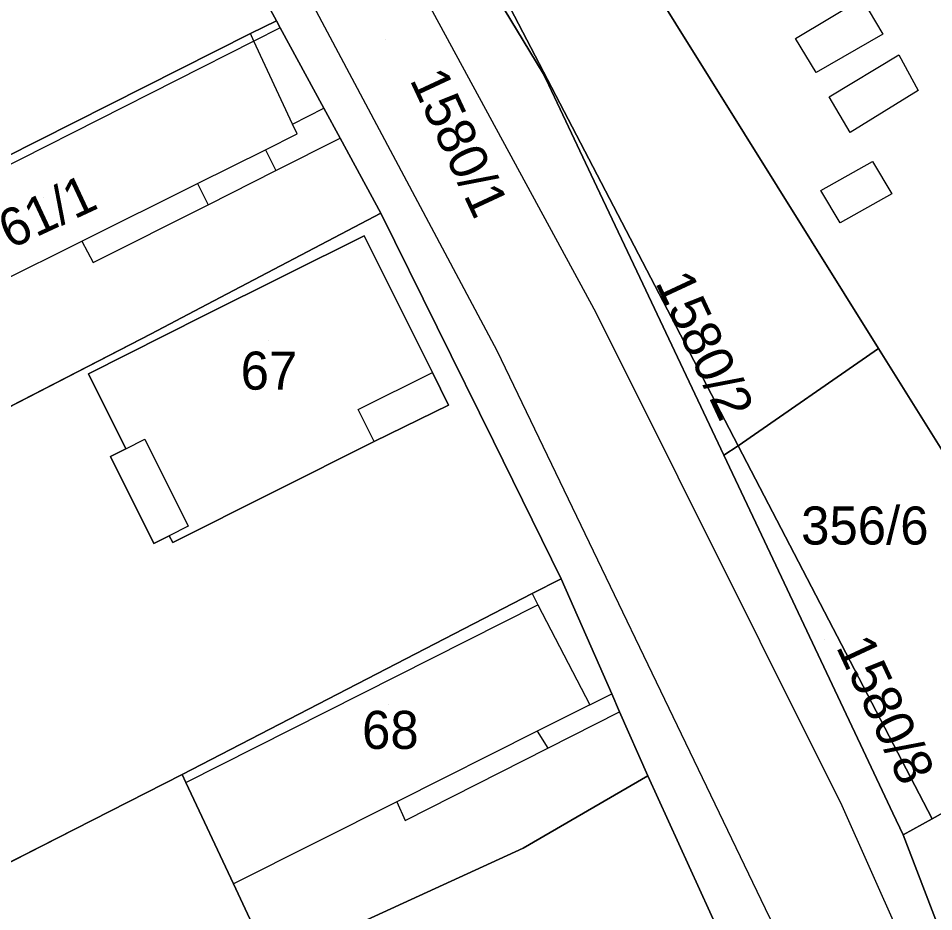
# Model space of a CAD drawing. Extents: x -263943 to -261149, y -1236934 to -1230686.
# Drawn here: x -262794.63 to -262746.54, y -1235729.03 to -1235682.08 of the extents above; entities that cross this region are included whole.
import ezdxf

# ---------------------------------------------------------------- set-up
doc = ezdxf.new("R2010")
doc.units = 0
for name, color, linetype in [('body_kn', 7, 'Continuous'), ('kladpar_druhypozemkov', 7, 'Continuous'), ('kladpar_hranice', 7, 'Continuous'), ('kladpar_parcelnecisla', 7, 'Continuous'), ('kladpar_plochy', 7, 'Continuous'), ('zappar_hrandruhpozemk', 7, 'Continuous')]:
    doc.layers.add(name, color=color, linetype=linetype)

msp = doc.modelspace()

# ---------------------------------------------------------------- linework, layer by layer
at = {"layer": 'body_kn'}
for p, q in [((-262781.07, -1235682.21), (-262781.07, -1235682.21)), ((-262782.43, -1235682.89), (-262782.43, -1235682.89)), ((-262780.87, -1235682.58), (-262780.87, -1235682.58)), ((-262780.87, -1235682.58), (-262780.87, -1235682.58)), ((-262749.22, -1235682.91), (-262749.22, -1235682.91)), ((-262782.25, -1235683.28), (-262782.25, -1235683.28)), ((-262782.25, -1235683.28), (-262782.25, -1235683.28)), ((-262753.81, -1235683.15), (-262753.81, -1235683.15)), ((-262753.81, -1235683.15), (-262753.81, -1235683.15)), ((-262748.38, -1235684.01), (-262748.38, -1235684.01)), ((-262767.05, -1235684.99), (-262767.05, -1235684.99)), ((-262752.71, -1235684.93), (-262752.71, -1235684.93)), ((-262766.76, -1235685.6), (-262766.76, -1235685.6)), ((-262752.04, -1235686.21), (-262752.04, -1235686.21)), ((-262752.04, -1235686.21), (-262752.04, -1235686.21)), ((-262747.36, -1235685.88), (-262747.36, -1235685.88)), ((-262778.58, -1235686.8), (-262778.58, -1235686.8)), ((-262778.58, -1235686.8), (-262778.58, -1235686.8)), ((-262780.22, -1235687.64), (-262780.22, -1235687.64)), ((-262779.98, -1235688.16), (-262779.98, -1235688.16)), ((-262779.98, -1235688.16), (-262779.98, -1235688.16)), ((-262750.94, -1235688.08), (-262750.94, -1235688.08)), ((-262777.72, -1235688.39), (-262777.72, -1235688.39)), ((-262781.65, -1235688.99), (-262781.65, -1235688.99)), ((-262781.65, -1235688.99), (-262781.65, -1235688.99)), ((-262749.75, -1235689.61), (-262749.75, -1235689.61)), ((-262749.75, -1235689.61), (-262749.75, -1235689.61)), ((-262781.1, -1235690.09), (-262781.1, -1235690.09)), ((-262781.1, -1235690.09), (-262781.1, -1235690.09)), ((-262785.21, -1235690.76), (-262785.21, -1235690.76)), ((-262785.21, -1235690.76), (-262785.21, -1235690.76)), ((-262764.24, -1235690.94), (-262764.24, -1235690.94)), ((-262752.47, -1235691.13), (-262752.47, -1235691.13)), ((-262752.47, -1235691.13), (-262752.47, -1235691.13)), ((-262748.74, -1235691.31), (-262748.74, -1235691.31)), ((-262784.66, -1235691.88), (-262784.66, -1235691.88)), ((-262775.58, -1235692.33), (-262775.58, -1235692.33)), ((-262751.46, -1235692.83), (-262751.46, -1235692.83)), ((-262776.46, -1235693.51), (-262776.46, -1235693.51)), ((-262776.46, -1235693.51), (-262776.46, -1235693.51)), ((-262791.29, -1235693.79), (-262791.29, -1235693.79)), ((-262790.7, -1235694.91), (-262790.7, -1235694.91)), ((-262790.7, -1235694.91), (-262790.7, -1235694.91)), ((-262761.83, -1235696.04), (-262761.83, -1235696.04)), ((-262785.06, -1235697.3), (-262785.06, -1235697.3)), ((-262784.86, -1235697.71), (-262784.86, -1235697.71)), ((-262764.3, -1235697.54), (-262764.3, -1235697.54)), ((-262760.31, -1235697.81), (-262760.31, -1235697.81)), ((-262787.65, -1235698.66), (-262787.65, -1235698.66)), ((-262769.48, -1235699.56), (-262769.48, -1235699.56)), ((-262749.44, -1235699.43), (-262749.44, -1235699.43)), ((-262749.44, -1235699.43), (-262749.44, -1235699.43)), ((-262772.87, -1235700.69), (-262772.87, -1235700.69)), ((-262790.95, -1235700.77), (-262790.95, -1235700.77)), ((-262776.77, -1235702.64), (-262776.77, -1235702.64)), ((-262772.03, -1235702.41), (-262772.03, -1235702.41)), ((-262787.99, -1235704.21), (-262787.99, -1235704.21)), ((-262775.93, -1235704.33), (-262775.93, -1235704.33)), ((-262775.93, -1235704.33), (-262775.93, -1235704.33)), ((-262769.67, -1235704.31), (-262769.67, -1235704.31)), ((-262756.81, -1235704.55), (-262756.81, -1235704.55)), ((-262788.98, -1235704.71), (-262788.98, -1235704.71)), ((-262788.98, -1235704.71), (-262788.98, -1235704.71)), ((-262757.57, -1235705.05), (-262757.57, -1235705.05)), ((-262757.57, -1235705.05), (-262757.57, -1235705.05)), ((-262789.78, -1235705.11), (-262789.78, -1235705.11)), ((-262785.7, -1235708.78), (-262785.7, -1235708.78)), ((-262786.7, -1235709.28), (-262786.7, -1235709.28)), ((-262787.51, -1235709.68), (-262787.51, -1235709.68)), ((-262786.52, -1235709.64), (-262786.52, -1235709.64)), ((-262755.44, -1235709.57), (-262755.44, -1235709.57)), ((-262766.12, -1235711.54), (-262766.12, -1235711.54)), ((-262766.12, -1235711.54), (-262766.12, -1235711.54)), ((-262767.63, -1235712.32), (-262767.63, -1235712.32)), ((-262767.63, -1235712.32), (-262767.63, -1235712.32)), ((-262767.33, -1235712.9), (-262767.33, -1235712.9)), ((-262767.33, -1235712.9), (-262767.33, -1235712.9)), ((-262763.46, -1235717.58), (-262763.46, -1235717.58)), ((-262764.61, -1235718.16), (-262764.61, -1235718.16)), ((-262764.61, -1235718.16), (-262764.61, -1235718.16)), ((-262763.04, -1235718.53), (-262763.04, -1235718.53)), ((-262763.04, -1235718.53), (-262763.04, -1235718.53)), ((-262767.38, -1235719.55), (-262767.38, -1235719.55)), ((-262767.38, -1235719.55), (-262767.38, -1235719.55)), ((-262766.82, -1235720.44), (-262766.82, -1235720.44)), ((-262766.82, -1235720.44), (-262766.82, -1235720.44)), ((-262750.25, -1235720.55), (-262750.25, -1235720.55)), ((-262786.02, -1235721.83), (-262786.02, -1235721.83)), ((-262761.56, -1235721.9), (-262761.56, -1235721.9)), ((-262785.83, -1235722.24), (-262785.83, -1235722.24)), ((-262785.83, -1235722.24), (-262785.83, -1235722.24)), ((-262774.75, -1235723.26), (-262774.75, -1235723.26)), ((-262751.37, -1235723.46), (-262751.37, -1235723.46)), ((-262774.31, -1235724.24), (-262774.31, -1235724.24)), ((-262748.69, -1235723.86), (-262748.69, -1235723.86)), ((-262746.62, -1235724.15), (-262746.62, -1235724.15)), ((-262748.15, -1235725), (-262748.15, -1235725)), ((-262768.11, -1235725.7), (-262768.11, -1235725.7)), ((-262783.33, -1235727.57), (-262783.33, -1235727.57)), ((-262755.38, -1235728.88), (-262755.38, -1235728.88))]:
    msp.add_line(p, q, dxfattribs=at)
at = {"layer": 'kladpar_druhypozemkov'}
for p, q in [((-262775.36, -1235683.21), (-262775.36, -1235683.21)), ((-262793.31, -1235691.48), (-262793.31, -1235691.48)), ((-262761.8, -1235695.41), (-262761.8, -1235695.41)), ((-262781.51, -1235699), (-262781.51, -1235699)), ((-262749.79, -1235708.34), (-262749.79, -1235708.34)), ((-262752.27, -1235714.73), (-262752.27, -1235714.73)), ((-262775.16, -1235718.13), (-262775.16, -1235718.13))]:
    msp.add_line(p, q, dxfattribs=at)
at = {"layer": 'kladpar_hranice'}
msp.add_line((-262746.62, -1235724.15), (-262748.15, -1235725), dxfattribs=at)
for points in [[(-262757.76, -1235730.23), (-262761.56, -1235721.9), (-262763.04, -1235718.53), (-262763.46, -1235717.58), (-262766.12, -1235711.54), (-262769.67, -1235704.31), (-262775.58, -1235692.33), (-262777.72, -1235688.39), (-262778.58, -1235686.8), (-262780.87, -1235682.58), (-262781.07, -1235682.21), (-262789.26, -1235667.17), (-262792.46, -1235658.93), (-262798.2, -1235647.88), (-262804.87, -1235637.59), (-262810.68, -1235627.46)], [(-262783.03, -1235655.9), (-262779.97, -1235661.3), (-262777.16, -1235666.77), (-262772.2, -1235676.47), (-262767.05, -1235684.99), (-262766.76, -1235685.6), (-262764.24, -1235690.94), (-262761.83, -1235696.04), (-262757.57, -1235705.05), (-262755.44, -1235709.57), (-262750.25, -1235720.55), (-262748.69, -1235723.86), (-262748.15, -1235725)], [(-262783.03, -1235655.9), (-262776.6, -1235666.53), (-262760.31, -1235697.81), (-262756.81, -1235704.55), (-262757.57, -1235705.05)], [(-262757.57, -1235705.05), (-262761.83, -1235696.04), (-262764.24, -1235690.94), (-262766.76, -1235685.6), (-262767.05, -1235684.99), (-262772.2, -1235676.47), (-262777.16, -1235666.77), (-262779.97, -1235661.3), (-262783.03, -1235655.9)], [(-262720.1, -1235733.26), (-262729.95, -1235715.09), (-262732.09, -1235716.21), (-262737.27, -1235718.92), (-262749.44, -1235699.43), (-262772.46, -1235662.54), (-262761.86, -1235657.8), (-262760.53, -1235660.05), (-262760.08, -1235659.76), (-262752.92, -1235671.25), (-262749.74, -1235669.21), (-262749.44, -1235669.67), (-262747.39, -1235668.34), (-262741.02, -1235678.09), (-262741.91, -1235678.69), (-262740.39, -1235680.9), (-262739.51, -1235680.4), (-262738.6, -1235681.79), (-262740.48, -1235683.02), (-262739.38, -1235684.55), (-262737.55, -1235683.39)], [(-262776.6, -1235666.53), (-262775.32, -1235663.82), (-262772.46, -1235662.54), (-262749.44, -1235699.43), (-262756.81, -1235704.55), (-262760.31, -1235697.81), (-262776.6, -1235666.53)], [(-262790.28, -1235666.57), (-262789.26, -1235667.17), (-262781.07, -1235682.21), (-262782.43, -1235682.89), (-262808.36, -1235695.96), (-262810.28, -1235692.12), (-262800.1, -1235686.99), (-262801.36, -1235681.47), (-262799.74, -1235680.63), (-262804.2, -1235671.36), (-262804.89, -1235669.92), (-262800.47, -1235667.73), (-262796.56, -1235666.3), (-262794.01, -1235666.05), (-262791.8, -1235665.97), (-262790.28, -1235666.57)], [(-262778.58, -1235686.8), (-262777.72, -1235688.39), (-262775.58, -1235692.33), (-262785.06, -1235697.3), (-262787.65, -1235698.66), (-262812.56, -1235711.51), (-262812.74, -1235711.14), (-262817.81, -1235700.76), (-262808.9, -1235696.24), (-262808.36, -1235695.96), (-262782.43, -1235682.89), (-262781.07, -1235682.21), (-262780.87, -1235682.58), (-262778.58, -1235686.8)], [(-262766.12, -1235711.54), (-262767.63, -1235712.32), (-262786.02, -1235721.83), (-262814.33, -1235736.25), (-262823.62, -1235717.22), (-262812.56, -1235711.51), (-262787.65, -1235698.66), (-262785.06, -1235697.3), (-262775.58, -1235692.33)], [(-262775.58, -1235692.33), (-262769.67, -1235704.31), (-262766.12, -1235711.54)], [(-262776.46, -1235693.51), (-262784.86, -1235697.71), (-262790.95, -1235700.77), (-262788.98, -1235704.71), (-262789.78, -1235705.11), (-262787.51, -1235709.68), (-262786.7, -1235709.28), (-262786.52, -1235709.64), (-262775.93, -1235704.33), (-262772.03, -1235702.41), (-262772.87, -1235700.69), (-262776.46, -1235693.51)], [(-262776.46, -1235693.51), (-262772.87, -1235700.69), (-262772.03, -1235702.41), (-262775.93, -1235704.33), (-262786.52, -1235709.64), (-262786.7, -1235709.28), (-262787.51, -1235709.68), (-262789.78, -1235705.11), (-262788.98, -1235704.71), (-262790.95, -1235700.77), (-262784.86, -1235697.71), (-262776.46, -1235693.51)], [(-262749.44, -1235699.43), (-262737.27, -1235718.92), (-262746.62, -1235724.15), (-262756.81, -1235704.55), (-262749.44, -1235699.43)], [(-262757.57, -1235705.05), (-262756.81, -1235704.55), (-262746.62, -1235724.15)], [(-262748.15, -1235725), (-262748.69, -1235723.86), (-262750.25, -1235720.55), (-262755.44, -1235709.57), (-262757.57, -1235705.05)], [(-262763.04, -1235718.53), (-262761.56, -1235721.9), (-262768.11, -1235725.7), (-262781.37, -1235731.77), (-262783.33, -1235727.57), (-262785.83, -1235722.24), (-262786.02, -1235721.83), (-262767.63, -1235712.32), (-262766.12, -1235711.54), (-262763.46, -1235717.58), (-262763.04, -1235718.53)], [(-262725.4, -1235736.37), (-262730.84, -1235739.04), (-262733.56, -1235733.97), (-262734.16, -1235734.29), (-262740.29, -1235737.58), (-262737.75, -1235742.44), (-262738, -1235742.56), (-262739.96, -1235743.52), (-262744.69, -1235734), (-262748.15, -1235725), (-262746.62, -1235724.15), (-262737.27, -1235718.92), (-262732.09, -1235716.21), (-262729.95, -1235715.09), (-262720.1, -1235733.26), (-262722.18, -1235734.48), (-262724.32, -1235735.84), (-262725.4, -1235736.37)], [(-262781.37, -1235731.77), (-262794.21, -1235737.25), (-262809.43, -1235744.92), (-262814.33, -1235736.25), (-262786.02, -1235721.83), (-262785.83, -1235722.24), (-262783.33, -1235727.57), (-262781.37, -1235731.77)], [(-262757.76, -1235730.23), (-262760.63, -1235731.63), (-262786.75, -1235744.4), (-262789.73, -1235745.83), (-262794.21, -1235737.25), (-262781.37, -1235731.77), (-262768.11, -1235725.7), (-262761.56, -1235721.9), (-262757.76, -1235730.23)], [(-262748.15, -1235725), (-262744.69, -1235734), (-262739.96, -1235743.52), (-262737.27, -1235749.43), (-262736.85, -1235750.36), (-262735.08, -1235754.25), (-262730.84, -1235763.57), (-262725.77, -1235775.21), (-262723.24, -1235780.94), (-262720.61, -1235786.88), (-262718.33, -1235792.03), (-262715.54, -1235798.09), (-262714.23, -1235800.95), (-262710.72, -1235808.59), (-262703.28, -1235824.99), (-262703.07, -1235825.33), (-262696.24, -1235836.4), (-262695.74, -1235837.22), (-262690.03, -1235845.09), (-262689.39, -1235845.98), (-262688.21, -1235847.33), (-262680.83, -1235855.76)]]:
    msp.add_lwpolyline(points, dxfattribs=at)
at = {"layer": 'kladpar_plochy'}
for p, q in [((-262785.06, -1235697.3), (-262775.58, -1235692.33)), ((-262775.58, -1235692.33), (-262769.67, -1235704.31)), ((-262776.46, -1235693.51), (-262784.86, -1235697.71)), ((-262772.87, -1235700.69), (-262776.46, -1235693.51)), ((-262787.65, -1235698.66), (-262785.06, -1235697.3)), ((-262784.86, -1235697.71), (-262790.95, -1235700.77)), ((-262812.56, -1235711.51), (-262787.65, -1235698.66)), ((-262772.03, -1235702.41), (-262772.87, -1235700.69)), ((-262790.95, -1235700.77), (-262788.98, -1235704.71)), ((-262775.93, -1235704.33), (-262772.03, -1235702.41)), ((-262786.52, -1235709.64), (-262775.93, -1235704.33)), ((-262769.67, -1235704.31), (-262766.12, -1235711.54)), ((-262788.98, -1235704.71), (-262789.78, -1235705.11)), ((-262789.78, -1235705.11), (-262787.51, -1235709.68)), ((-262787.51, -1235709.68), (-262786.7, -1235709.28)), ((-262786.7, -1235709.28), (-262786.52, -1235709.64)), ((-262766.12, -1235711.54), (-262767.63, -1235712.32)), ((-262767.63, -1235712.32), (-262786.02, -1235721.83)), ((-262746.62, -1235724.15), (-262737.27, -1235718.92)), ((-262786.02, -1235721.83), (-262814.33, -1235736.25)), ((-262748.15, -1235725), (-262746.62, -1235724.15)), ((-262744.69, -1235734), (-262748.15, -1235725))]:
    msp.add_line(p, q, dxfattribs=at)
for points in [[(-262808.03, -1235616.78), (-262795.62, -1235636.77), (-262795.19, -1235636.51), (-262783.03, -1235655.9), (-262779.97, -1235661.3), (-262777.16, -1235666.77), (-262772.2, -1235676.47), (-262767.05, -1235684.99), (-262766.76, -1235685.6), (-262764.24, -1235690.94), (-262761.83, -1235696.04), (-262757.57, -1235705.05), (-262755.44, -1235709.57), (-262750.25, -1235720.55), (-262748.69, -1235723.86), (-262748.15, -1235725), (-262744.69, -1235734)], [(-262757.76, -1235730.23), (-262761.56, -1235721.9), (-262763.04, -1235718.53), (-262763.46, -1235717.58), (-262766.12, -1235711.54), (-262769.67, -1235704.31), (-262775.58, -1235692.33), (-262777.72, -1235688.39), (-262778.58, -1235686.8), (-262780.87, -1235682.58), (-262781.07, -1235682.21), (-262789.26, -1235667.17), (-262792.46, -1235658.93), (-262798.2, -1235647.88), (-262804.87, -1235637.59), (-262810.68, -1235627.46)], [(-262737.27, -1235718.92), (-262749.44, -1235699.43), (-262772.46, -1235662.54), (-262761.86, -1235657.8), (-262760.53, -1235660.05), (-262760.08, -1235659.76), (-262752.92, -1235671.25), (-262749.74, -1235669.21), (-262749.44, -1235669.67), (-262747.39, -1235668.34), (-262741.02, -1235678.09)]]:
    msp.add_lwpolyline(points, dxfattribs=at)
for points in [[(-262783.03, -1235655.9), (-262776.6, -1235666.53), (-262760.31, -1235697.81), (-262756.81, -1235704.55), (-262757.57, -1235705.05), (-262761.83, -1235696.04), (-262764.24, -1235690.94), (-262766.76, -1235685.6), (-262767.05, -1235684.99), (-262772.2, -1235676.47), (-262777.16, -1235666.77), (-262779.97, -1235661.3)], [(-262776.6, -1235666.53), (-262775.32, -1235663.82), (-262772.46, -1235662.54), (-262749.44, -1235699.43), (-262756.81, -1235704.55), (-262760.31, -1235697.81)], [(-262790.28, -1235666.57), (-262789.26, -1235667.17), (-262781.07, -1235682.21), (-262782.43, -1235682.89), (-262808.36, -1235695.96), (-262810.28, -1235692.12), (-262800.1, -1235686.99), (-262801.36, -1235681.47), (-262799.74, -1235680.63), (-262804.2, -1235671.36), (-262804.89, -1235669.92), (-262800.47, -1235667.73), (-262796.56, -1235666.3), (-262794.01, -1235666.05), (-262791.8, -1235665.97)], [(-262778.58, -1235686.8), (-262777.72, -1235688.39), (-262775.58, -1235692.33), (-262785.06, -1235697.3), (-262787.65, -1235698.66), (-262812.56, -1235711.51), (-262812.74, -1235711.14), (-262817.81, -1235700.76), (-262808.9, -1235696.24), (-262808.36, -1235695.96), (-262782.43, -1235682.89), (-262781.07, -1235682.21), (-262780.87, -1235682.58)], [(-262776.46, -1235693.51), (-262772.87, -1235700.69), (-262772.03, -1235702.41), (-262775.93, -1235704.33), (-262786.52, -1235709.64), (-262786.7, -1235709.28), (-262787.51, -1235709.68), (-262789.78, -1235705.11), (-262788.98, -1235704.71), (-262790.95, -1235700.77), (-262784.86, -1235697.71)], [(-262749.44, -1235699.43), (-262737.27, -1235718.92), (-262746.62, -1235724.15), (-262756.81, -1235704.55)], [(-262746.62, -1235724.15), (-262748.15, -1235725), (-262748.69, -1235723.86), (-262750.25, -1235720.55), (-262755.44, -1235709.57), (-262757.57, -1235705.05), (-262756.81, -1235704.55)], [(-262763.04, -1235718.53), (-262761.56, -1235721.9), (-262768.11, -1235725.7), (-262781.37, -1235731.77), (-262783.33, -1235727.57), (-262785.83, -1235722.24), (-262786.02, -1235721.83), (-262767.63, -1235712.32), (-262766.12, -1235711.54), (-262763.46, -1235717.58)], [(-262781.37, -1235731.77), (-262794.21, -1235737.25), (-262809.43, -1235744.92), (-262814.33, -1235736.25), (-262786.02, -1235721.83), (-262785.83, -1235722.24), (-262783.33, -1235727.57)], [(-262757.76, -1235730.23), (-262760.63, -1235731.63), (-262786.75, -1235744.4), (-262789.73, -1235745.83), (-262794.21, -1235737.25), (-262781.37, -1235731.77), (-262768.11, -1235725.7), (-262761.56, -1235721.9)]]:
    msp.add_lwpolyline(points, close=True, dxfattribs=at)
at = {"layer": 'zappar_hrandruhpozemk'}
for p, q in [((-262769.48, -1235699.56), (-262779.11, -1235681.46)), ((-262782.25, -1235683.28), (-262782.43, -1235682.89)), ((-262749.22, -1235682.91), (-262752.71, -1235684.93)), ((-262780.22, -1235687.64), (-262782.25, -1235683.28)), ((-262752.71, -1235684.93), (-262753.81, -1235683.15)), ((-262750.94, -1235688.08), (-262752.04, -1235686.21)), ((-262747.36, -1235685.88), (-262750.94, -1235688.08)), ((-262780.22, -1235687.64), (-262778.58, -1235686.8)), ((-262779.98, -1235688.16), (-262780.22, -1235687.64)), ((-262781.1, -1235690.09), (-262777.72, -1235688.39)), ((-262781.65, -1235688.99), (-262781.1, -1235690.09)), ((-262752.47, -1235691.13), (-262749.75, -1235689.61)), ((-262749.75, -1235689.61), (-262748.74, -1235691.31)), ((-262785.21, -1235690.76), (-262784.66, -1235691.88)), ((-262751.46, -1235692.83), (-262752.47, -1235691.13)), ((-262748.74, -1235691.31), (-262751.46, -1235692.83)), ((-262796.22, -1235696.25), (-262791.29, -1235693.79)), ((-262791.29, -1235693.79), (-262790.7, -1235694.91)), ((-262776.77, -1235702.64), (-262772.87, -1235700.69)), ((-262775.93, -1235704.33), (-262776.77, -1235702.64)), ((-262788.98, -1235704.71), (-262787.99, -1235704.21)), ((-262787.99, -1235704.21), (-262785.7, -1235708.78)), ((-262785.7, -1235708.78), (-262786.7, -1235709.28)), ((-262767.63, -1235712.32), (-262767.33, -1235712.9)), ((-262785.83, -1235722.24), (-262767.33, -1235712.9)), ((-262764.61, -1235718.16), (-262763.46, -1235717.58)), ((-262766.82, -1235720.44), (-262763.04, -1235718.53)), ((-262767.38, -1235719.55), (-262766.82, -1235720.44)), ((-262774.31, -1235724.24), (-262766.82, -1235720.44)), ((-262774.75, -1235723.26), (-262783.33, -1235727.57)), ((-262774.75, -1235723.26), (-262774.31, -1235724.24)), ((-262751.37, -1235723.46), (-262742.26, -1235743.85))]:
    msp.add_line(p, q, dxfattribs=at)
for points in [[(-262778.66, -1235671.02), (-262764.3, -1235697.54), (-262751.37, -1235723.46)], [(-262753.81, -1235683.15), (-262750.32, -1235681.04), (-262749.22, -1235682.91)], [(-262780.87, -1235682.58), (-262782.25, -1235683.28), (-262798.6, -1235691.56)], [(-262752.04, -1235686.21), (-262748.38, -1235684.01), (-262747.36, -1235685.88)], [(-262791.29, -1235693.79), (-262785.21, -1235690.76), (-262781.65, -1235688.99), (-262779.98, -1235688.16)], [(-262790.7, -1235694.91), (-262784.66, -1235691.88), (-262781.1, -1235690.09)], [(-262737.73, -1235767.2), (-262747.1, -1235745.96), (-262755.38, -1235728.88), (-262769.48, -1235699.56)], [(-262767.33, -1235712.9), (-262764.61, -1235718.16), (-262767.38, -1235719.55), (-262774.75, -1235723.26)]]:
    msp.add_lwpolyline(points, dxfattribs=at)

# ---------------------------------------------------------------- texts
at = {"layer": 'kladpar_parcelnecisla'}
for s, rotation, p in [('1580/1', 295, (-262774.09, -1235685.312)), ('61/1', 25, (-262795.061, -1235694.234)), ('1580/2', 295, (-262761.189, -1235695.963)), ('1580/8', 295, (-262751.693, -1235715.11))]:
    msp.add_text(s, height=2, rotation=rotation, dxfattribs=at).set_placement(p)
for s, p in [('67', (-262782.951, -1235701.6)), ('356/6', (-262753.507, -1235709.74)), ('68', (-262776.572, -1235720.48))]:
    msp.add_text(s, height=2, dxfattribs=at).set_placement(p)

doc.saveas('drawing.dxf')
